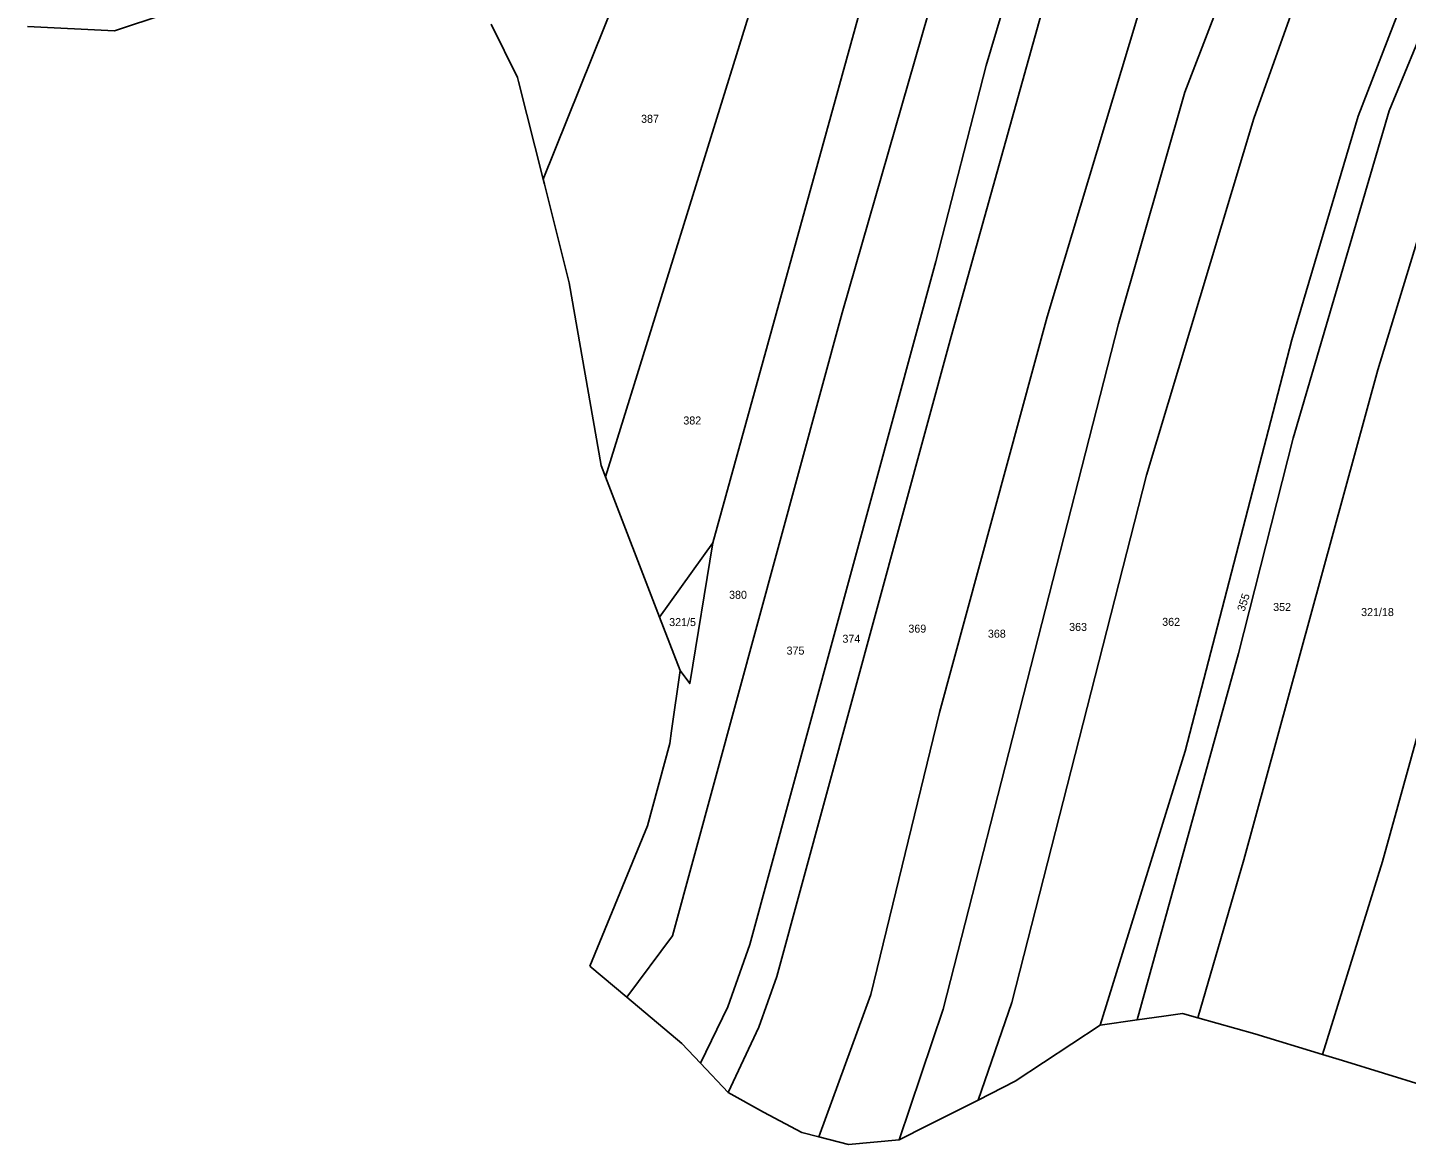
# Model space of a CAD drawing. Extents: x -746176 to -739709, y -1128407 to -1124482.
# Drawn here: x -743895.5 to -743602.7, y -1128009.6 to -1127772.3 of the extents above; entities that cross this region are included whole.
import ezdxf

# ---------------------------------------------------------------- set-up
doc = ezdxf.new("R2010")
doc.units = 0
doc.layers.add('Hranice parcel', color=7, linetype='Continuous')
doc.layers.add('Parcelní čísla', color=7, linetype='Continuous')

msp = doc.modelspace()

# ---------------------------------------------------------------- linework, layer by layer
at = {"layer": 'Hranice parcel'}
for p, q in [((-743732.64, -1127738.2), (-743772.75, -1127867.77)), ((-743711.36, -1127741.87), (-743749.96, -1127881.78)), ((-743761.26, -1127742.79), (-743786, -1127804.52)), ((-743791.23, -1127783.7), (-743786, -1127804.52)), ((-743786, -1127804.52), (-743785.74, -1127805.57)), ((-743785.74, -1127805.57), (-743780.48, -1127826.53)), ((-743780.48, -1127826.53), (-743773.7, -1127865.3)), ((-743773.7, -1127865.3), (-743772.75, -1127867.77)), ((-743772.75, -1127867.77), (-743761.28, -1127897.56)), ((-743749.96, -1127881.78), (-743761.28, -1127897.56)), ((-743761.28, -1127897.56), (-743760.44, -1127899.72)), ((-743760.44, -1127899.72), (-743756.9, -1127908.92)), ((-743756.9, -1127908.92), (-743758.74, -1127921.72)), ((-743776.13, -1127971.68), (-743768.26, -1127978.29)), ((-743659.84, -1127983.12), (-743654.23, -1127982.34)), ((-743667.73, -1127984.22), (-743659.84, -1127983.12)), ((-743646.98, -1127982.69), (-743634.85, -1127986.07)), ((-743634.85, -1127986.07), (-743620.48, -1127990.48)), ((-743620.48, -1127990.48), (-743616.23, -1127991.79)), ((-743752.61, -1127992.31), (-743746.7, -1127998.56)), ((-743616.23, -1127991.79), (-743598.82, -1127997.13)), ((-743704.36, -1128005.57), (-743693.63, -1128000.15)), ((-743710.41, -1128008.62), (-743704.36, -1128005.57)), ((-743731.1, -1128007.03), (-743727.47, -1128007.97))]:
    msp.add_line(p, q, dxfattribs=at)
for points in [[(-743697.14, -1127744.72), (-743722.54, -1127832.92), (-743758.56, -1127965.24), (-743768.26, -1127978.29)], [(-743682.17, -1127747.48), (-743691.92, -1127780.31), (-743702.59, -1127822), (-743742.13, -1127967.1), (-743746.82, -1127980.32), (-743752.61, -1127992.31)], [(-743674.43, -1127748.6), (-743699.34, -1127837.9), (-743736.36, -1127973.94), (-743740.21, -1127984.65), (-743746.7, -1127998.56)], [(-743654.42, -1127752.06), (-743678.95, -1127833.74), (-743701.86, -1127917.81), (-743716.39, -1127977.76), (-743727.47, -1128007.97)], [(-743638.13, -1127755.73), (-743649.76, -1127786.02), (-743663.84, -1127835.21), (-743701.08, -1127980.88), (-743710.41, -1128008.62)], [(-743844.2, -1127758.32), (-743866.16, -1127769.33), (-743877.07, -1127772.96), (-743895.51, -1127772.06)], [(-743623.67, -1127759.6), (-743635.09, -1127791.61), (-743657.85, -1127867.39), (-743686.5, -1127979.4), (-743693.63, -1128000.15)], [(-743603.54, -1127766.74), (-743612.96, -1127791.11), (-743627.05, -1127838.6), (-743649.69, -1127926.04), (-743667.73, -1127984.22)], [(-743597.33, -1127768.16), (-743606.36, -1127789.97), (-743626.72, -1127859.49), (-743638.35, -1127905.26), (-743659.84, -1127983.12)], [(-743797.09, -1127771.57), (-743791.43, -1127782.89), (-743791.23, -1127783.7)], [(-743587.1, -1127780.87), (-743593.35, -1127794.42), (-743608.73, -1127844.98), (-743637.18, -1127949.14), (-743646.98, -1127982.69)], [(-743620.48, -1127990.48), (-743607.74, -1127949.5), (-743573.69, -1127826.51)], [(-743756.9, -1127908.92), (-743754.87, -1127911.67), (-743749.96, -1127881.78)], [(-743758.74, -1127921.72), (-743759.13, -1127924.43), (-743763.85, -1127941.89), (-743776.13, -1127971.68)], [(-743768.26, -1127978.29), (-743756.53, -1127988.15), (-743752.61, -1127992.31)], [(-743654.23, -1127982.34), (-743650.24, -1127981.78), (-743646.98, -1127982.69)], [(-743693.63, -1128000.15), (-743685.74, -1127996.16), (-743667.73, -1127984.22)], [(-743746.7, -1127998.56), (-743739.19, -1128002.73), (-743731.1, -1128007.03)], [(-743727.47, -1128007.97), (-743721.18, -1128009.59), (-743710.41, -1128008.62)]]:
    msp.add_lwpolyline(points, dxfattribs=at)

# ---------------------------------------------------------------- texts
at = {"layer": 'Parcelní čísla'}
for s, p in [('387', (-743765.22, -1127792.51)), ('382', (-743756.24, -1127856.61)), ('380', (-743746.53, -1127893.65)), ('352', (-743630.98, -1127896.24)), ('321/18', (-743612.3, -1127897.32)), ('321/5', (-743759.25, -1127899.45)), ('369', (-743708.45, -1127900.84)), ('368', (-743691.56, -1127901.92)), ('363', (-743674.31, -1127900.48)), ('362', (-743654.55, -1127899.4)), ('374', (-743722.46, -1127902.99)), ('375', (-743734.32, -1127905.51))]:
    msp.add_text(s, height=1.7, dxfattribs=at).set_placement(p)
msp.add_text('355', height=1.7, rotation=72, dxfattribs=at).set_placement((-743637.08, -1127896.46))

doc.saveas('drawing.dxf')
